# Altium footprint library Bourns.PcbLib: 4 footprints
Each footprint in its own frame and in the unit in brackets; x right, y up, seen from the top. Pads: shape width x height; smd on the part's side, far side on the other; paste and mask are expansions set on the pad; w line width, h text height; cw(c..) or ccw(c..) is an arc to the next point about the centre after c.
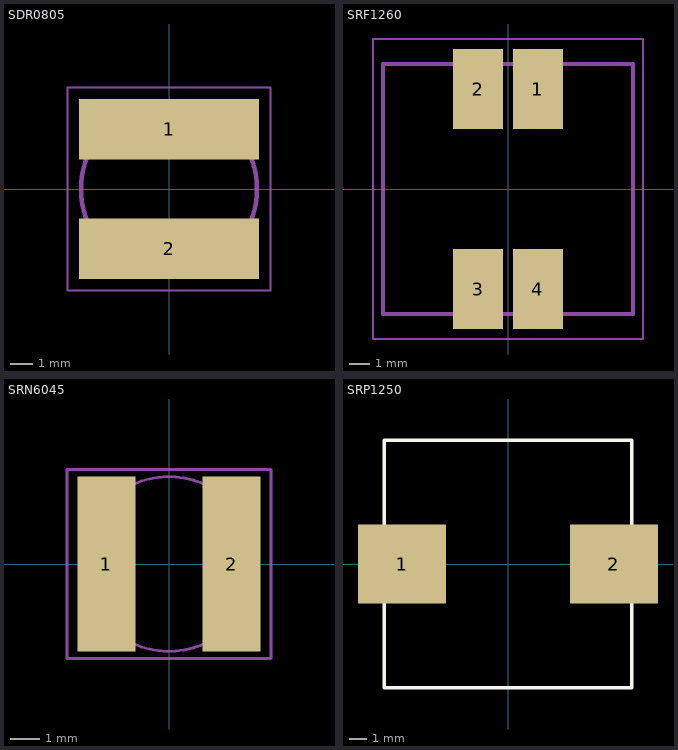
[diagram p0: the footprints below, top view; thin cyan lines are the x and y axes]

## SDR0805 [mm] "Surface-mount Inductor"
height 5.3
pads (2):
  rect 8x2.7 smd: 1(0,2.65) 2(0,-2.65)
Mechanical 13:
  circle w0.2: c0,0 r3.9
Mechanical 15:
  lines w0.1: -4.5,-4.5 -4.5,4.5 4.5,4.5 4.5,-4.5 -4.5,-4.5
3D body: height 5.3, standoff 0, extent -3.869,-3.892 3.9,3.892

## SRF1260 [mm]
pads (4):
  rect 2.5x4 smd: 1(1.5,5) 2(-1.5,5) 3(-1.5,-5) 4(1.5,-5)
Mechanical 13:
  lines w0.2: -6.25,-6.25 6.25,-6.25 6.25,6.25 -6.25,6.25 -6.25,-6.25
Mechanical 15:
  lines w0.1: -6.75,-7.5 6.75,-7.5 6.75,7.5 -6.75,7.5 -6.75,-7.5
3D body: height 6, standoff 0, extent -6.25,-6.25 6.25,6.25

## SRN6045 [mm] "Surface mount inductor, 6mm x 6mm"
height 4.5
pads (2):
  rect 2x6 smd: 1(-2.15,0) 2(2.15,0)
Mechanical 13:
  circle w0.1: c0,0 r3
Mechanical 15:
  lines w0.1: -3.5,-3.25 -3.5,3.25 3.5,3.25 3.5,-3.25 -3.5,-3.25
3D body: height 4.5, standoff 0, extent -2.976,-2.994 3,2.994

## SRP1250 [mm] "Surface mount inductor"
height 5.9
pads (2):
  rect 5x4.5 smd mask+0: 1(-6,0) 2(6,0)
Top Overlay:
  lines w0.2: -7,-7 7,-7 7,7 -7,7 -7,-7
3D body: height 5.9, standoff 0, extent -7,-7 7,7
